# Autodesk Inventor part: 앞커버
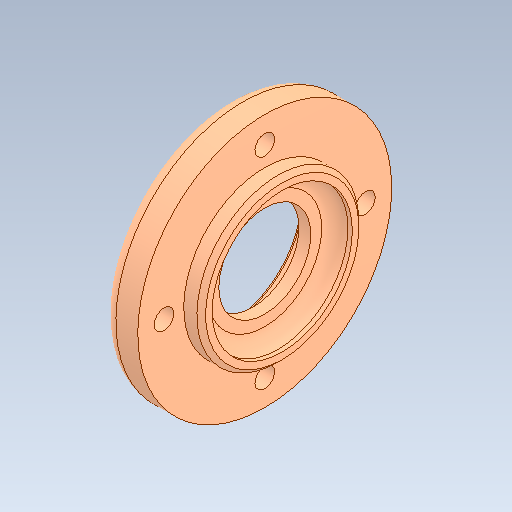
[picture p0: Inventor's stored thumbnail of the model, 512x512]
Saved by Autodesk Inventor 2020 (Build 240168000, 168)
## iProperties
Created: 2024-08
Part Number: 앞커버
Material: 알루미늄 6061
Document SubType Name: Modeling
Designer: oem
Density: 2.7 g/cm^3
Appearance: 기본값
Author: jhkim
Sending System: Autodesk Inventor 2025
Preprocessor: ST-DEVELOPER v20
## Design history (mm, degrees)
node "앞커버1"
node "솔리드2"
node "솔리드1"
